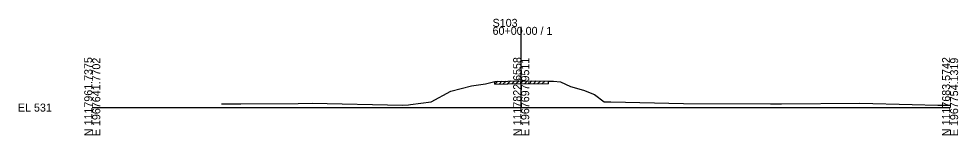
# Model space of a CAD drawing. Extents: x 974 to 1303, y 990 to 14518.
# Drawn here: x 974.3 to 1302.8, y 5990.3 to 6031.1 of the extents above; entities that cross this region are included whole.
import ezdxf

# ---------------------------------------------------------------- set-up
doc = ezdxf.new("R2010")
doc.units = 0
for name, color, linetype in [('Level 10', 7, 'Continuous'), ('Level 60', 7, 'Continuous'), ('Level 61', 7, 'Continuous'), ('Level 63', 7, 'Continuous')]:
    doc.layers.add(name, color=color, linetype=linetype)

msp = doc.modelspace()

# ---------------------------------------------------------------- linework, layer by layer
at = {"layer": 'Level 60'}
for p, q in [((1137.53, 6008.36), (1140.76, 6009.2)), ((1140.76, 6009.2), (1149.84, 6009.43)), ((1149.84, 6009.43), (1149.84, 6009.43)), ((1149.84, 6009.43), (1159.4, 6009.28)), ((1159.4, 6009.28), (1161.35, 6009.25)), ((1161.35, 6009.25), (1163.76, 6009.01)), ((1163.76, 6009.01), (1167.27, 6007.36)), ((1118.58, 6002.03), (1125.35, 6005.73)), ((1125.35, 6005.73), (1132.68, 6007.6)), ((1132.68, 6007.6), (1137.53, 6008.36)), ((1167.27, 6007.36), (1171.76, 6006.12)), ((1171.76, 6006.12), (1175.67, 6004.61)), ((1175.67, 6004.61), (1179, 6002.04)), ((1045.17, 6001.32), (1051.92, 6001.37)), ((1051.92, 6001.37), (1072.05, 6001.47)), ((1072.05, 6001.47), (1076.9, 6001.58)), ((1076.9, 6001.58), (1108.55, 6000.87)), ((1108.55, 6000.87), (1110.57, 6000.93)), ((1110.57, 6000.93), (1111.33, 6001.03)), ((1111.33, 6001.03), (1118.58, 6002.03)), ((1179, 6002.04), (1181.4, 6002.06)), ((1181.4, 6002.06), (1206.78, 6001.43)), ((1206.78, 6001.43), (1237.2, 6001.29)), ((1237.2, 6001.29), (1239.87, 6001.32)), ((1239.87, 6001.32), (1241.06, 6001.3)), ((1241.06, 6001.3), (1268.42, 6001.59)), ((1268.42, 6001.59), (1286.77, 6001.08)), ((1286.77, 6001.08), (1295.72, 6000.82)), ((1295.72, 6000.82), (1300, 6000.9))]:
    msp.add_line(p, q, dxfattribs=at)
at = {"layer": 'Level 61'}
for p, q in [((1140.76, 6008.2), (1141.78, 6009.23)), ((1140.76, 6008.2), (1140.76, 6009.2)), ((1142.26, 6008.24), (1143.28, 6009.26)), ((1143.76, 6008.28), (1144.78, 6009.3)), ((1145.26, 6008.32), (1146.28, 6009.34)), ((1146.76, 6008.35), (1147.78, 6009.38)), ((1148.26, 6008.39), (1149.28, 6009.42)), ((1149.76, 6008.43), (1150.74, 6009.42)), ((1151.26, 6008.41), (1152.24, 6009.39)), ((1152.76, 6008.38), (1153.74, 6009.37)), ((1154.26, 6008.36), (1155.24, 6009.34)), ((1155.76, 6008.34), (1156.74, 6009.32)), ((1157.26, 6008.31), (1158.24, 6009.29)), ((1159.4, 6009.28), (1159.4, 6008.28)), ((1140.76, 6008.2), (1149.84, 6008.43)), ((1140.76, 6008.2), (1140.76, 6008.2)), ((1149.84, 6008.43), (1159.4, 6008.28)), ((1149.84, 6008.43), (1149.84, 6008.43)), ((1159.4, 6008.28), (1159.4, 6008.28))]:
    msp.add_line(p, q, dxfattribs=at)
at = {"layer": 'Level 63'}
for p, q in [((1150, 6000), (1150, 6028.3)), ((1000, 6000), (1150, 6000)), ((1150, 6000), (1300, 6000))]:
    msp.add_line(p, q, dxfattribs=at)

# ---------------------------------------------------------------- texts
at = {"layer": 'Level 10'}
msp.add_text('540.43', height=0.9, rotation=90, dxfattribs=at).set_placement((1149.95, 6009.93))
at = {"layer": 'Level 63'}
for s, p in [('S103', (1140, 6028.3)), ('60+00.00 / 1', (1140, 6025.5)), ('EL 531', (974, 5998.6))]:
    msp.add_text(s, height=2.8, dxfattribs=at).set_placement(p)
for s, p in [('N 1117961.7375', (1000, 5990)), ('E 1967641.7702', (1002.8, 5990)), ('N 1117822.6558', (1150, 5990)), ('E 1967697.9511', (1152.8, 5990)), ('N 1117683.5742', (1300, 5990)), ('E 1967754.1319', (1302.8, 5990))]:
    msp.add_text(s, height=2.8, rotation=90, dxfattribs=at).set_placement(p)

doc.saveas('drawing.dxf')
